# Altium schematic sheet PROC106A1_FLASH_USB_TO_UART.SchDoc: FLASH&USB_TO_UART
size 431 x 279 mm; Date: Not shown in title block; ApprovedBy: Not shown in title block; CheckedBy: Not shown in title block; Author: Not shown in title block; CompanyName: Not shown in title block; DrawnBy: Antony/Anand Ram; Engineer: Not shown in title block; Organization: Not shown in title block; Address1: Not shown in title block; Address2: Not shown in title block; Address3: Not shown in title block; Address4: Not shown in title block; DocumentNumber: 6; Revision: Use project parameter SCH_Rev; SheetNumber: 6; SheetTotal: 12; PageSetup: Record=PageOptions¦CenterHorizontal=True¦CenterVertical=True¦PrintScale=1.00¦XCorrection=1.00¦YCorrection=1.00¦PrintKind=0¦BorderSize=5000000¦LeftOffset=0¦BottomOffset=0¦Orientation=2¦PaperLength=1000¦PaperWidth=1000¦Scale=100¦PaperSource=15¦PrintQuality=600¦MediaType=1¦DitherType=10¦PaperKind=Letter¦PrintScaleMode=1
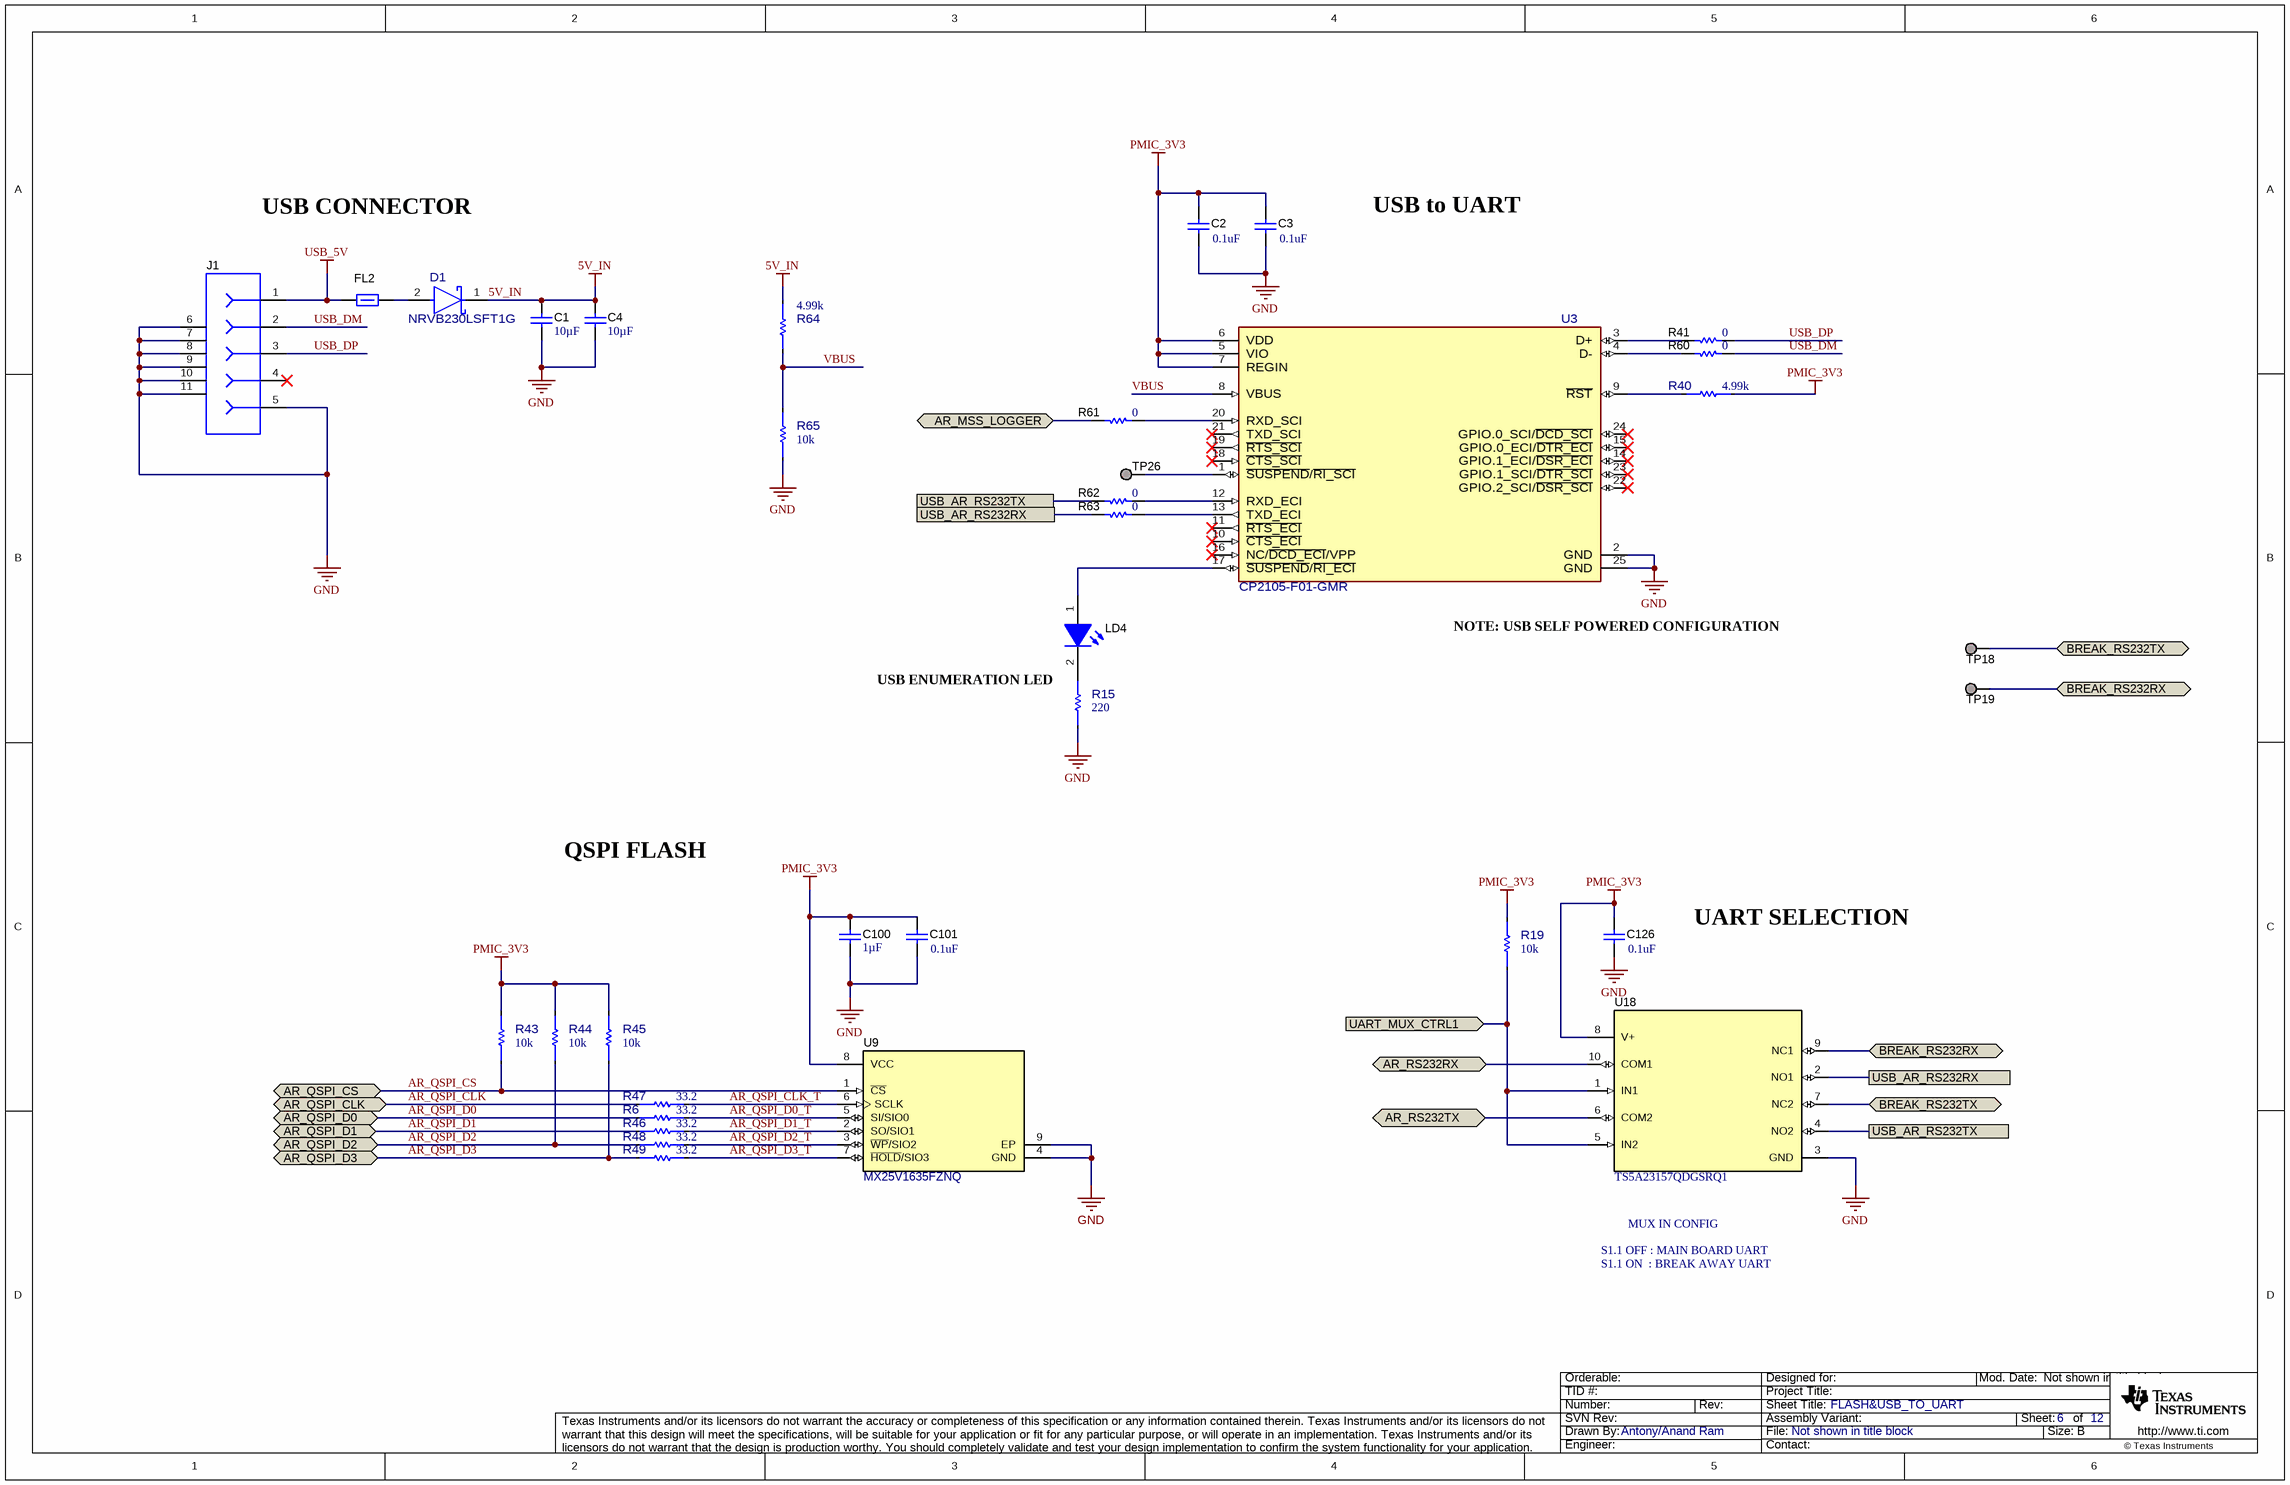
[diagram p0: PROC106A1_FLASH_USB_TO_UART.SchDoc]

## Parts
C1  Cap_F: 10µF  [0805L]  (hidden comment: GCM21BR71A106KE22L)
C2  ValueDisplayed: 0.1uF  [0402L]  (hidden comment: GCM155R71C104KA55D)
C3  ValueDisplayed: 0.1uF  [0402L]  (hidden comment: GCM155R71C104KA55D)
C4  Cap_F: 10µF  [0805L]  (hidden comment: GCM21BR71A106KE22L)
C100  Cap_F: 1µF  [0603L]  (hidden comment: GCM188R71C105KA64D)
C101  ValueDisplayed: 0.1uF  [0402L]  (hidden comment: GCM155R71C104KA55D)
C126  ValueDisplayed: 0.1uF  [0402L]  (hidden comment: GCM155R71C104KA55D)
D1  NRVB230LSFT1G  [FP-NRVB230LSFT1G_SOD-123F-MFG]
FL2  BLM15PD300SZ1D  [0402L]  (value not drawn)
J1  105017-0001  [CONN_105017-0001]  (value not drawn)
LD4  APHHS1005CGCK  [APHHS1005_Green]  (value not drawn)
R6  value 33.2  [FP-ERJ-1GNF33R2C_0201-IPC_C]  (hidden comment: ERJ-1GNF33R2C)
R15  value 220  [FP-ERJ-1GNJ221C_0201-IPC_C]  (hidden comment: ERJ-1GNJ221C)
R19  value 10k  [FP-ERA-1AEB103C_0201-IPC_C]  (hidden comment: ERA-1AEB103C)
R40  value 4.99k  [FP-ERJ-1GNF4991C_0201-IPC_C]  (hidden comment: ERJ-1GNF4991C)
R41  ValueDisplayed: 0  [0201L]  (hidden comment: ERJ-1GN0R00C)
R43  value 10k  [FP-ERA-1AEB103C_0201-IPC_C]  (hidden comment: ERA-1AEB103C)
R44  value 10k  [FP-ERA-1AEB103C_0201-IPC_C]  (hidden comment: ERA-1AEB103C)
R45  value 10k  [FP-ERA-1AEB103C_0201-IPC_C]  (hidden comment: ERA-1AEB103C)
R46  value 33.2  [FP-ERJ-1GNF33R2C_0201-IPC_C]  (hidden comment: ERJ-1GNF33R2C)
R47  value 33.2  [FP-ERJ-1GNF33R2C_0201-IPC_C]  (hidden comment: ERJ-1GNF33R2C)
R48  value 33.2  [FP-ERJ-1GNF33R2C_0201-IPC_C]  (hidden comment: ERJ-1GNF33R2C)
R49  value 33.2  [FP-ERJ-1GNF33R2C_0201-IPC_C]  (hidden comment: ERJ-1GNF33R2C)
R60  ValueDisplayed: 0  [0201L]  (hidden comment: ERJ-1GN0R00C)
R61  ValueDisplayed: 0  [0201L]  (hidden comment: ERJ-1GN0R00C)
R62  ValueDisplayed: 0  [0201L]  (hidden comment: ERJ-1GN0R00C)
R63  ValueDisplayed: 0  [0201L]  (hidden comment: ERJ-1GN0R00C)
R64  value 4.99k  [FP-ERJ-1GNF4991C_0201-IPC_C]  (hidden comment: ERJ-1GNF4991C)
R65  value 10k  [FP-ERA-1AEB103C_0201-IPC_C]  (hidden comment: ERA-1AEB103C)
TP18  TESTPOINT  [TP_25MIL-SMT]  (value not drawn)  (no BOM)
TP19  TESTPOINT  [TP_25MIL-SMT]  (value not drawn)  (no BOM)
TP26  TESTPOINT  [TP_25MIL-SMT]  (value not drawn)  (no BOM)
U3  CP2105-F01-GMR  [FP-CP2105-F01-GMR_QFN24-EP-IPC_A]
U9  MX25V1635FZNQ  [WSON-8L_6x5MM_EP]
U18  TS5A23157QDGSRQ1  [DGS0010A_L]

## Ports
AR_MSS_LOGGER (bidir), AR_QSPI_CLK (bidir), AR_QSPI_CS (bidir), AR_QSPI_D0 (bidir), AR_QSPI_D1 (bidir), AR_QSPI_D2 (bidir), AR_QSPI_D3 (bidir), AR_RS232RX (bidir), AR_RS232TX (bidir), BREAK_RS232RX (bidir), BREAK_RS232TX (bidir), UART_MUX_CTRL1 (in), USB_AR_RS232RX, USB_AR_RS232TX

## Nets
5V_IN: C1.2 C4.1 D1.1(CATHODE) R64.1
GND: C1.1 C2.2 C3.2 C4.2 C100.1 C101.1 C126.1 J1.5 J1.6 J1.7 J1.8 J1.9 J1.10 J1.11 R15.1 R65.1 U3.2(GND) U3.25(GND) U9.4(GND) U9.9(EP) U18.3(GND)
PMIC_3V3: C2.1 C3.1 C100.2 C101.2 C126.2 R19.2 R40.1 R43.2 R44.2 R45.2 U3.5(VIO) U3.6(VDD) U3.7(REGIN) U9.8(VCC) U18.8(V+)
USB_5V: FL2.1 J1.1
AR_MSS_LOGGER: R61.1 ; port AR_MSS_LOGGER
AR_QSPI_CLK: R47.1 ; port AR_QSPI_CLK
AR_QSPI_CLK_T: R47.2 U9.6(SCLK)
AR_QSPI_CS: R43.1 U9.1(~{CS}) ; port AR_QSPI_CS
AR_QSPI_D0: R6.1 ; port AR_QSPI_D0
AR_QSPI_D0_T: R6.2 U9.5(SI/SIO0)
AR_QSPI_D1: R46.1 ; port AR_QSPI_D1
AR_QSPI_D1_T: R46.2 U9.2(SO/SIO1)
AR_QSPI_D2: R44.1 R48.1 ; port AR_QSPI_D2
AR_QSPI_D2_T: R48.2 U9.3(~{WP}/SIO2)
AR_QSPI_D3: R45.1 R49.1 ; port AR_QSPI_D3
AR_QSPI_D3_T: R49.2 U9.7(~{HOLD}/SIO3)
AR_RS232RX: U18.10(COM1) ; port AR_RS232RX
AR_RS232TX: U18.6(COM2) ; port AR_RS232TX
BREAK_RS232RX: TP19.1 U18.9(NC1) ; port BREAK_RS232RX
BREAK_RS232TX: TP18.1 U18.7(NC2) ; port BREAK_RS232TX
UART_MUX_CTRL1: R19.1 U18.1(IN1) U18.5(IN2) ; port UART_MUX_CTRL1
USB_AR_RS232RX: R63.1 U18.2(NO1) ; port USB_AR_RS232RX
USB_AR_RS232TX: R62.1 U18.4(NO2) ; port USB_AR_RS232TX
USB_DM: J1.2 R60.2
USB_DP: J1.3 R41.2
VBUS: R64.2 R65.2 U3.8(VBUS)
NetD1_2: D1.2(ANODE) FL2.2
NetLD4_1: LD4.1(A) U3.17(~{SUSPEND}/~{RI_ECI})
NetLD4_2: LD4.2(K) R15.2
NetR40_2: R40.2 U3.9(~{RST})
NetR41_1: R41.1 U3.3(D+)
NetR60_1: R60.1 U3.4(D-)
NetR61_2: R61.2 U3.20(RXD_SCI)
NetR62_2: R62.2 U3.12(RXD_ECI)
NetR63_2: R63.2 U3.13(TXD_ECI)
NetTP26_1: TP26.1 U3.1(~{SUSPEND}/~{RI_SCI})

Not connected (* = marked no-connect by the designer): J1 4*; U3 10(~{CTS_ECI})* 11(~{RTS_ECI})* 14(GPIO.1_ECI/~{DSR_ECI})* 15(GPIO.0_ECI/~{DTR_ECI})* 16(NC/~{DCD_ECI}/VPP)* 18(~{CTS_SCI})* 19(~{RTS_SCI})* 21(TXD_SCI)* 22(GPIO.2_SCI/~{DSR_SCI})* 23(GPIO.1_SCI/~{DTR_SCI})* 24(GPIO.0_SCI/~{DCD_SCI})*

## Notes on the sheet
- USB CONNECTOR
- USB to UART
- (near U3) NOTE: USB SELF POWERED CONFIGURATION
- USB ENUMERATION LED
- QSPI FLASH
- UART SELECTION
- MUX IN CONFIG
- S1.1 ON  : BREAK AWAY UART
- S1.1 OFF : MAIN BOARD UART

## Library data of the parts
C1 C4 = CMP-0008017-2: CAP, CERM, 10 uF, 10 V, +/- 10%, X7R, 0805; Manufacturer: MuRata; Value: 10uF; AEC Category: Q200; Cap_Case: 0805; Polarized: N; SizeArea_mm2: 2.5; SizeAreaWB_mm2: 6.75; SizeX_mm: 2; SizeY_mm: 1.25; SizeZ_mm: 1.45; TaMax_C: 125°C; TaMin_C: -55°C; U/M: EA; Value1: Unknown; Value2: 10V
C2 C3 C101 C126 = CMP-0006351-2: CAP, CERM, 0.1 uF, 16 V, +/- 10%, X7R, 0402; Manufacturer: MuRata; Cap_F: 100nF; SizeZ_mm: 0.6; VDC_V: 16V; AEC Category: Q200; Cap_Case: 0402; Polarized: N; SizeArea_mm2: 0.5; SizeAreaWB_mm2: 3; SizeX_mm: 1; TaMax_C: 125°C; TaMin_C: -55°C; U/M: EA; Value1: Unknown; Value: 0.1uF
C100 = CMP-0007136-5: CAP, CERM, 1 uF, 16 V, +/- 10%, X7R, AEC-Q200 Grade 1, 0603; Manufacturer: MuRata; AEC Qualified: Y; SizeZ_mm: 1; VDC_V: 16V; AEC Category: Q200; Cap_Case: 0603; Polarized: N; SizeArea_mm2: 1.28; SizeAreaWB_mm2: 4.68; SizeX_mm: 1.6; SizeY_mm: 0.8; TaMax_C: 125°C; TaMin_C: -55°C; U/M: EA; Value1: Unknown; Value: 1uF
D1 = CMP-0090508-1: Diode Schottky 30V 2A Surface Mount SOD-123FL; Manufacturer: ON Semiconductor; TJmax_C: 125°C; SizeZ_mm: 0.98mm; AEC Qualified: Yes; AEC Grade: Grade 1; Max Surge Forward Current: 40A; Peak Reverse Current: 1mA; Standoff Height: 0mm
FL2 = CMP-0078934-1: Inductor, Ferrite Bead, Ferrite, 2.2 A, 0.035 ohm, AEC-Q200 Grade 1, SMD; Manufacturer: MuRata; AEC Category: Q200; AEC Grade: 1; AEC Qualified: Y; DCR_ohm: 0.035; Imax_A: 2.2A; SizeArea_mm2: 0.5; SizeAreaWB_mm2: 3; SizeZ_mm: 0.6
J1 = CMP-0055293-1: Connector, Receptacle, Micro-USB Type B, R/A, Bottom Mount SMT; Manufacturer: Molex; CNHeader: FALSE; CompType: USB; CT: TRUE; Gender: Female; Green_Lifecycle: Active; Green_REACh: Passed
LD4 = CMP-0067682-2: LED, Green, SMD; Manufacturer: Kingbright; Angle: 120.0; Power_TotalModule: 75mW; SizeZ_mm: 0.6; Vf_V: 2.1V; Vr_V: 5V; Io_A: 20mA; Ir_A: 10µA; SizeArea_mm2: 0.5; SizeAreaWB_mm2: 3.0; SizeX_mm: 1.0; Tjmax_C: 85°C; Value1: 0.075W
R6 R46-R49 = CMP-0089575-2: Res Thick Film 0201 33.2 Ohm 1% 0.05W(1/20W) ±200ppm/C Pad SMD Automotive T/R; Manufacturer: Panasonic; AEC Grade: Grade 1; AEC Qualified: Yes; Power_W: 50mW; SizeZ_mm: 0.26mm; TempCo: 200ppm/°C; VDC_V: 25V
R15 = CMP-0090501-1: 220 Ohms ±5% 0.05W, 1/20W Chip Resistor 0201 (0603 Metric) Automotive AEC-Q200 Thick Film; Manufacturer: Panasonic Electronic Components; AEC Grade: Grade 1; AEC Qualified: Yes; Power_W: 50mW; SizeZ_mm: 0.26mm; TempCo: 200ppm/°C; VDC_V: 25V
R19 R43-R45 R65 = CMP-0090084-1: RES SMD 10K OHM 0.1% 1/20W 0201; Manufacturer: Panasonic; AEC Qualified: No; Power_W: 50mW; SizeZ_mm: 0.26mm; TempCo: 25ppm/°C; VDC_V: 25V
R40 R64 = CMP-0090497-1: 4.99 kOhms ±1% 0.05W, 1/20W Chip Resistor 0201 (0603 Metric) Automotive AEC-Q200 Thick Film; Manufacturer: Panasonic Electronic Components; AEC Grade: Grade 1; AEC Qualified: Yes; Power_W: 50mW; SizeZ_mm: 0.26mm; TempCo: 200ppm/°C; VDC_V: 25V
R41 R60-R63 = CMP-0065361-1: RES, 0, 5%, .05 W, AEC-Q200 Grade 0, 0201; Manufacturer: Panasonic; AEC Qualified: Y; Power_W: 50mW; SizeZ_mm: 0.26; TempCo: ppm/C; AEC Category: Q200; EIA_Code: E24; Green_Lifecycle: Not Set; Green_REACh: Incomplete; SizeArea_mm2: 0.18; SizeX_mm: 0.6; SizeY_mm: 0.3; U/M: EA; Value2: .05W; Value: 0; Value_Code: 0000
TP18 TP19 TP26 = CMP-0078143-3: TEST POINT.  No entry in BOM.
U3 = CMP-0087172-1: I/O Controller Interface IC USB to Dual UART bridge; Manufacturer: Silicon Labs; SizeZ_mm: 0.8mm
U9 = CMP-0079267-1: 2.3V-3.6V, 16M-BIT [x 1/x 2/x 4] CMOS FLASH Memory, WSON-8; Manufacturer: Macronix International Co., LTD; SizeArea_mm2: 30; SizeAreaWB_mm2: 56; SizeX_mm: 6; SizeY_mm: 5; SizeZ_mm: 0.8
U18 = CMP-0074341-1: Automotive Catalog Dual 15-Ohm SPDT Analog Switch, DGS0010A (VSSOP-10); Alternate Manufacturer: Texas Instruments; CompType: IC; SizeArea_mm2: 14.7; SizeAreaWB_mm2: 23.6; SizeX_mm: 4.9; SizeY_mm: 3.0; SizeZ_mm: 1.1; U/M: EA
